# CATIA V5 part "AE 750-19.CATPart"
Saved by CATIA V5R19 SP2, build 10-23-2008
Part number: AE 750-19
Bounding box of the stored display mesh (mm): x -24.865 to 24.865, y -24.997 to 24.997, z 0 to 88
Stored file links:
  C:\Users\Bora\Desktop\3D Katı model\AE serisi\AE 750\AE 750-19.CATPart
  C:\Program Files\Dassault Systemes\B19\intel_a\reffiles\standard\MetricThickPitch.txt
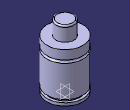
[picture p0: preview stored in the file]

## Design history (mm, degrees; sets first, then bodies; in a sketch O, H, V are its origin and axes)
Body1 (main body)
  Sketch1 on yz-plane, origin (0, 0, 0), H (0, 1, 0), V (0, 0, 1)
    point P1 (25, 51.5)
    point P8 (25, 55.5)
    point P9 (12.5, 86)
    point P11 (12.5, 86)
    point P13 (25, 55.5)
    point P14 (25, 51.5)
    line L1 (25, 51.5) -> (25, 8)
    line L2 (25, 4) -> (25, 0)
    line L3 (21.5, 8) -> (21.5, 4)
    line L4 (25, 68) -> (25, 55.5)
    line L5 (12.5, 86) -> (12.5, 68)
    arc A1 centre (10.5, 86) radius 2 from (12.5, 86) to (10.5, 88) ccw
    arc A2 centre (25, 53.5) radius 2 from (25, 55.5) to (25, 51.5) ccw
    line L6 (10.5, 88) -> (0, 88)
    point P15 (0, 88)
    line L7 (12.5, 68) -> (25, 68)
    line L8 (0, 0) -> (25, 0)
    line L9 (21.5, 8) -> (25, 8)
    line L10 (21.5, 4) -> (25, 4)
    coincidence: P15 V, P1 P14, P8 P13, P9 P11
    tangency: L6 A1
    horizontal: L7 H, L8 H, L9 H, L10 H
  Shaft1: profile Sketch1, axis Sketch1.V, angle 360
  Sketch2 on face of Shaft1 from Sketch1.L8, origin (0, 0, 0), H (1, 0, 0), V (0, -1, 0)
    point P1 (10, 0)
    distance P1 V = 10
  Hole1: placed by Sketch2, at (10, 0, 0) direction (0, 0, 1), diameter 6.647, depth 13, threaded "M8", thread diameter 8, thread depth 13, pitch 1.25
  CircPattern1: of Hole1, instances 2, angular step 180, axis from xy-plane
